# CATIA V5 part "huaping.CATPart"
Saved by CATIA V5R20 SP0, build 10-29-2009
Part number: Part2
Material "Multicoloured Flag"
Material "DS Light Blue": density 7860 kg/m3, Young's modulus 2e+11 Pa, Poisson ratio 0.266
Bounding box of the stored display mesh (mm): x -186.271 to 34.998, y -70.037 to 61.876, z 0 to 132.474
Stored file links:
  C:\Users\Machenike\Desktop\zuoye\huaping.CATPart
  D:\CATIAR20\win_b64\startup\materials\Catalog.CATMaterial
  D:\CATIAR20\win_b64\startup\materials\blue_env_512x512.jpg
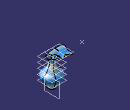
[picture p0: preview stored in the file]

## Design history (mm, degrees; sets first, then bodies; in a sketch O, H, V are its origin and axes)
Set1
  Plane1: type Offset, RefPlane xy-plane, Offset 20
  Plane2: type Offset, RefPlane Plane1, Offset 20
  Plane3: type Offset, RefPlane Plane2, Offset 20
  Plane4: type Offset, RefPlane Plane3, Offset 20
  Sketch1 on Plane4, origin (0, 0, 80), H (1, 0, 0), V (0, 1, 0)
    circle A1 centre (0, 0) radius 10
    radius A1 = 10
  Sketch2 on Plane3, origin (0, 0, 60), H (1, 0, 0), V (0, 1, 0)
    circle A1 centre (0, 0) radius 17.5
    radius A1 = 17.5
  Sketch3 on Plane2, origin (0, 0, 40), H (1, 0, 0), V (0, 1, 0)
    circle A1 centre (0, 0) radius 35
    radius A1 = 35
  Sketch4 on Plane1, origin (0, 0, 20), H (1, 0, 0), V (0, 1, 0)
    circle A1 centre (0, 0) radius 25
    radius A1 = 25
  Sketch5 on xy-plane, origin (0, 0, 0), H (1, 0, 0), V (0, 1, 0)
    circle A1 centre (0, 0) radius 15
    radius A1 = 15
  Plane5: type Offset, RefPlane Plane4, Offset 20
  Sketch6 on Plane5, origin (0, 0, 100), H (1, 0, 0), V (0, 1, 0)
    circle A1 centre (0, 0) radius 17.5
    radius A1 = 17.5
Body1 (main body), material "Multicoloured Flag"
  Loft1: solid, Sections (Sketch6; Sketch1; Sketch2; Sketch3; Sketch4; Sketch5)
  Shell1: IntOffset 1, Face face of Loft1, ExtOffset 0
  Point1: type OnPlane, Support Plane1, H -186.271, V -70.037, Direction (1, 0, 0)
  Sketch7 on yz-plane, origin (0, 0, 0), H (0, 1, 0), V (0, 0, 1)
    line L1 (10, 0) -> (10, 20)
    arc A1 centre (-45, 35) radius 57.0088 from (10, 20) to (0, 70) ccw
    point P4 (0, 70)
    spline S1 through (0, 70) (0, 110) (10, 130) (30, 130)
    point P5 (0, 70)
    vertical: L1 V
    coincidence: A1 O, P5 P4
  Pad1: profile Sketch7, direction (1, 0, 0), length 2, thin wall 1
  Plane6: type OffsetPt, RefPlane Plane5, RefPoint vertex [end face of Pad1 | face of Pad1 | face of Pad1]
  Fillet1: radius 0.3, on edge [face of Shell1 | face of Loft1]; edge [face of Loft1 | face of Loft1]
  Sketch8 on Plane6, origin (0, 0, 129.0758), H (1, 0, 0), V (0, 1, 0)
    spline S1 through (0, 50) (20, 60) (20, 30) (30, 20) (0, 10) (-30, 20) (-20, 40) (-20, 60) (0, 50)
    point P1 (0, 10)
    point P2 (0, 50)
    point P3 (0, 50)
    coincidence: P1 V, P2 P3
  Pad2: profile Sketch8, direction (0, 0, 1), length 2
Body2, material "DS Light Blue"
  Sketch9 on yz-plane, origin (0, 0, 0), H (0, 1, 0), V (0, 0, 1)
    line L1 (-28.4237, 29.5494) -> (-15.2826, 2.1435)
    line L2 (-15.2826, 2.1435) -> (-2.9379, 2.1435)
    line L3 (-2.9379, 2.1435) -> (-2.9379, 29.5494)
    line L4 (-2.9379, 29.5494) -> (-28.4237, 29.5494)
    horizontal: L2 H, L4 H
    vertical: L3 V
  Shaft1: profile Sketch9, axis Sketch9.V, angle 360, thin wall 1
